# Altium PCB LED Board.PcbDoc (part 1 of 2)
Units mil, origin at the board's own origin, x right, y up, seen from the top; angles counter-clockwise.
Board outline 11968.5 x 3779.53 mil, 2 copper layers (Top Layer, Bottom Layer); 272 components, 796 nets, 779 pads, 57 vias.
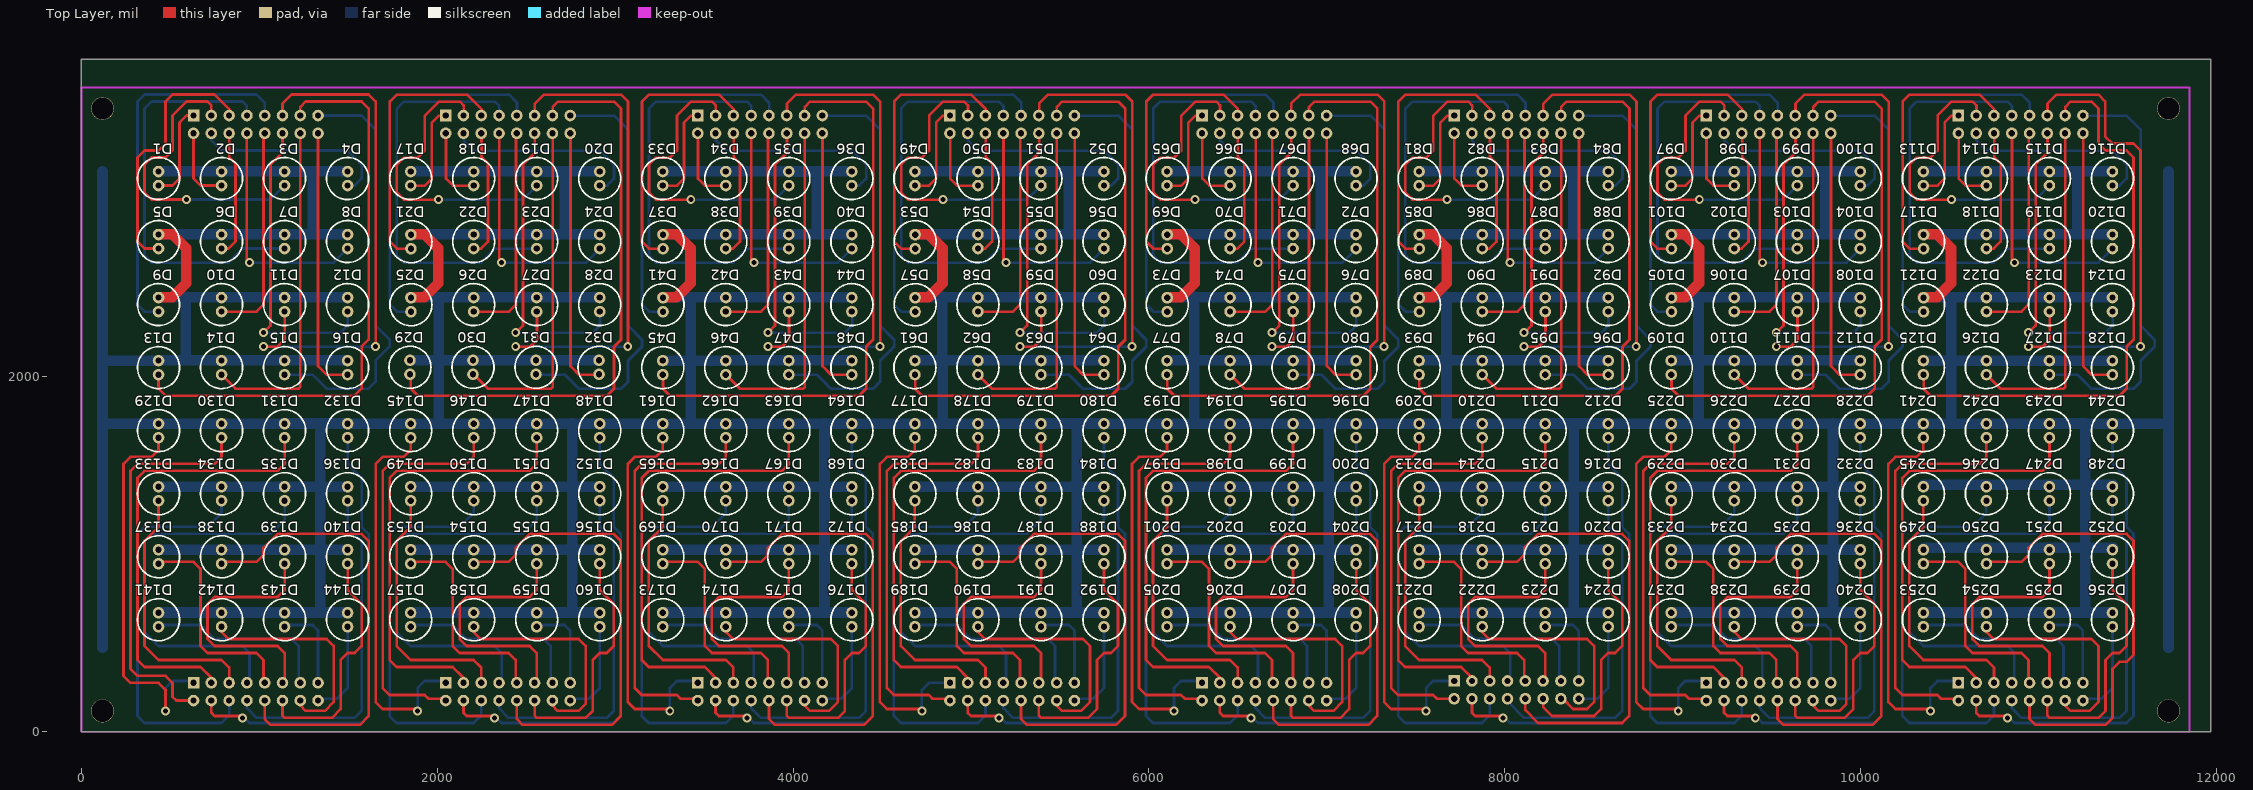
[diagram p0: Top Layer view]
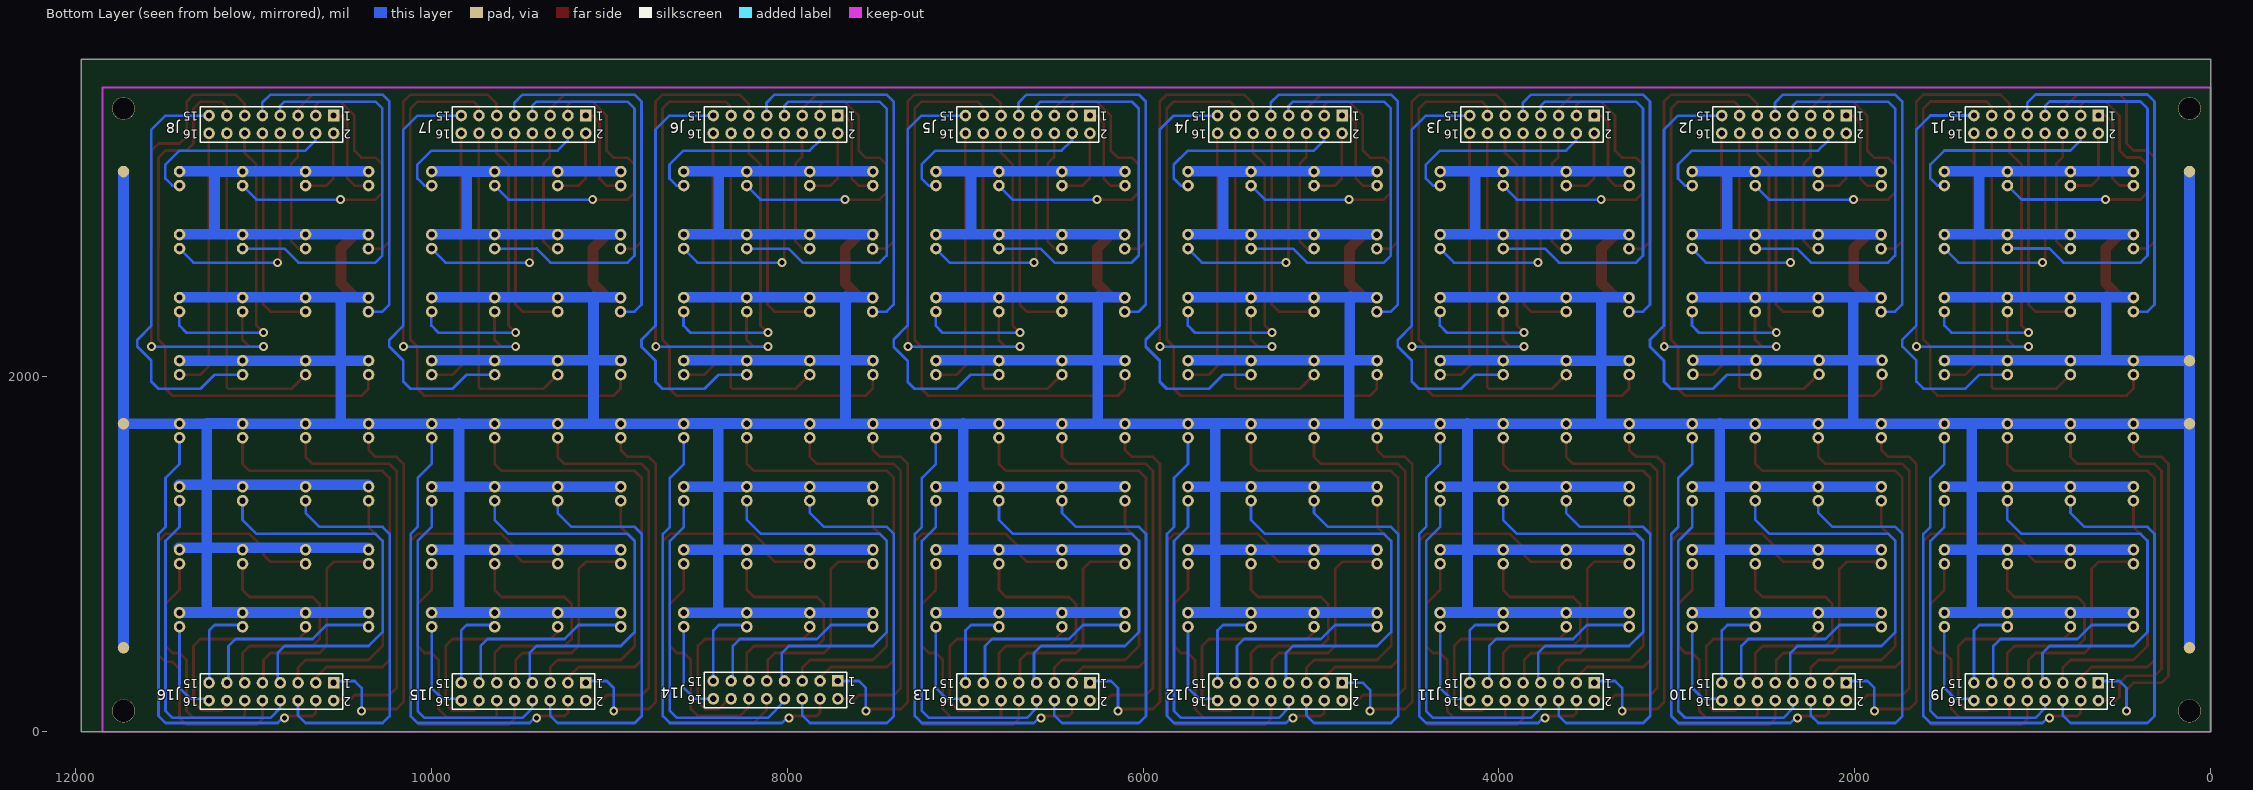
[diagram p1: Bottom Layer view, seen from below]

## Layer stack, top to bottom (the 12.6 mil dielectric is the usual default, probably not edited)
Top Layer: signal copper 1.4
Dielectric: dielectric 12.6, FR-4, Dk 4.8
Bottom Layer: signal copper 1.4

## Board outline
0,0 11968.5,0 11968.5,3779.53 7559.06,3779.53 0,3779.53

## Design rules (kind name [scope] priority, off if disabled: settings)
Clearance [All] p1: gap=10
ComponentClearance [All] p1: gap=10 collisioncheckmode=0
PolygonConnect [All] p1: connectstyle=Relief reliefconductorwidth=10 reliefentries=4 polygonreliefangle="90 Angle"
RoutingLayers [All] p1: top layer=Horizontal bottom layer=Vertical
RoutingVias [All] p1: holewidth=28 width=50 viastyle="Through Hole" minholewidth=28 minwidth=50 maxholewidth=28 maxwidth=50
SolderMaskExpansion [All] p1: expansion=4
TestPointUsage [All] p1: valid=0 allowmultiple=FALSE
Testpoint [All] p1: side=15 testpointundercomponent=TRUE minsize=40 maxsize=100 preferedsize=60 minholesize=0 maxholesize=40 preferedholesize=32 testpointgrid=1 style=1023 order=1234567890
Width Width_1 [InNetClass('A[1..256]')] p1: maxlimit=15 minlimit=15 preferedwidth=15
Width [(InNet('+5'))] p2: maxlimit=60 minlimit=60 preferedwidth=60
16 further rules are at their usual default settings.

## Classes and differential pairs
component class "Input Headers 1": J1 J2 J3 J4 J5 J6 J7 J8 J9
component class "Input Headers 2": J10 J11 J12 J13 J14 J15 J16
component class "Res & Diode 2": D1 D2 D3 D4 D5 D6 D7 D8 D9 D10 D11 D12 D13 D14 D15 D16 D17 D18 D19 D20 D21 D22 D23 D24 D25 D26 D27 D28 D29 D30 D31 D32 D33 D34 D35 D36 D37 D38 D39 D40 D41 D42 D43 D44 D45 D46 D47 D48 D49 D50 D51 D52 D53 D54 D55 D56 D57 D58 D59 D60 D61 D62 D63 D64 D65 D66 D67 D68 D69 D70 D71 D72 D73 D74 D75 D76 D77 D78 D79 D80 D81 D82 D83 D84 D85 D86 D87 D88 D89 D90 D91 D92 D93 D94 D95 D96 D97 D98 D99 D100 D101 D102 D103 D104 D105 D106 D107 D108 D109 D110 D111 D112 D113 D114 D115 D116 D117 D118 D119 D120 D121 D122 D123 D124 D125 D126 D127 D128 D129 D130 D131 D132 D133 D134 D135 D136 D137 D138 D139 D140 D141 D142 D143 D144 D145 D146 D147 D148 D149 D150 D151 D152 D153 D154 D155 D156 D157 D158 D159 D160
net class A[1..256]: A1 A2 A3 A4 A5 A6 A7 A8 A9 A10 A11 A12 A13 A14 A15 A16 A17 A18 A19 A20 A21 A22 A23 A24 A25 A26 A27 A28 A29 A30 A31 A32 A33 A34 A35 A36 A37 A38 A39 A40 A41 A42 A43 A44 A45 A46 A47 A48 A49 A50 A51 A52 A53 A54 A55 A56 A57 A58 A59 A60 A61 A62 A63 A64 A65 A66 A67 A68 A69 A70 A71 A72 A73 A74 A75 A76 A77 A78 A79 A80 A81 A82 A83 A84 A85 A86 A87 A88 A89 A90 A91 A92 A93 A94 A95 A96 A97 A98 A99 A100 A101 A102 A103 A104 A105 A106 A107 A108 A109 A110 A111 A112 A113 A114 A115 A116 A117 A118 A119 A120 A121 A122 A123 A124 A125 A126 A127 A128 A129 A130 A131 A132 A133 A134 A135 A136 A137 A138 A139 A140 A141 A142 A143 A144 A145 A146 A147 A148 A149 A150 A151 A152 A153 A154 A155 A156 A157 A158 A159 A160 A161 A162 A163 A164 A165 A166 A167 A168 A169 A170 A171 A172 A173 A174 A175 A176 A177 A178 A179 A180 A181 A182 A183 A184 A185 A186 A187 A188 A189 A190 A191 A192 A193 A194 A195 A196 A197 A198 A199 A200 A201 A202 A203 A204 A205 A206 A207 A208 A209 A210 A211 A212 A213 A214 A215 A216 A217 A218 A219 A220 A221 A222 A223 A224 A225 A226 A227 A228 A229 A230 A231 A232 A233 A234 A235 A236 A237 A238 A239 A240 A241 A242 A243 A244 A245 A246 A247 A248 A249 A250 A251 A252 A253 A254 A255 A256
component class "Res & Diode 3": D161 D162 D163 D164 D165 D166 D167 D168 D169 D170 D171 D172 D173 D174 D175 D176 D177 D178 D179 D180 D181 D182 D183 D184 D185 D186 D187 D188 D189 D190 D191 D192 D193 D194 D195 D196 D197 D198 D199 D200 D201 D202 D203 D204 D205 D206 D207 D208 D209 D210 D211 D212 D213 D214 D215 D216 D217 D218 D219 D220 D221 D222 D223 D224 D225 D226 D227 D228 D229 D230 D231 D232 D233 D234 D235 D236 D237 D238 D239 D240 D241 D242 D243 D244 D245 D246 D247 D248 D249 D250 D251 D252 D253 D254 D255 D256 R21 R22 R23 R24 R25 R26 R27 R28 R29 R30

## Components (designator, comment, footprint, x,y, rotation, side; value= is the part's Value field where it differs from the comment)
D1 "LED" LED 433.07,3149.61 r180 top
D2 "LED" LED 787.4,3149.61 r180 top
D3 "LED" LED 1141.73,3149.61 r180 top
D4 "LED" LED 1496.06,3149.61 r180 top
D5 "LED" LED 433.07,2795.28 r180 top
D6 "LED" LED 787.4,2795.28 r180 top
D7 "LED" LED 1141.73,2795.28 r180 top
D8 "LED" LED 1496.06,2795.28 r180 top
D9 "LED" LED 433.07,2440.95 r180 top
D10 "LED" LED 787.4,2440.94 r180 top
D11 "LED" LED 1141.73,2440.94 r180 top
D12 "LED" LED 1496.06,2440.94 r180 top
D13 "LED" LED 433.07,2086.61 r180 top
D14 "LED" LED 787.4,2086.61 r180 top
D15 "LED" LED 1141.73,2086.61 r180 top
D16 "LED" LED 1496.06,2086.61 r180 top
D17 "LED" LED 1850.39,3149.61 r180 top
D18 "LED" LED 2204.72,3149.61 r180 top
D19 "LED" LED 2559.06,3149.61 r180 top
D20 "LED" LED 2913.39,3149.61 r180 top
D21 "LED" LED 1851.81,2794.65 r180 top
D22 "LED" LED 2204.72,2795.28 r180 top
D23 "LED" LED 2559.06,2795.28 r180 top
D24 "LED" LED 2913.39,2795.28 r180 top
D25 "LED" LED 1851.81,2440.32 r180 top
D26 "LED" LED 2204.72,2440.94 r180 top
D27 "LED" LED 2559.06,2440.94 r180 top
D28 "LED" LED 2913.39,2440.94 r180 top
D29 "LED" LED 1846.46,2088.5 r180 top
D30 "LED" LED 2200.79,2088.5 r180 top
D31 "LED" LED 2555.12,2088.5 r180 top
D32 "LED" LED 2909.45,2088.5 r180 top
D33 "LED" LED 3267.72,3149.61 r180 top
D34 "LED" LED 3622.05,3149.61 r180 top
D35 "LED" LED 3976.38,3149.61 r180 top
D36 "LED" LED 4330.71,3149.61 r180 top
D37 "LED" LED 3269.13,2794.65 r180 top
D38 "LED" LED 3622.05,2795.28 r180 top
D39 "LED" LED 3976.38,2795.28 r180 top
D40 "LED" LED 4330.71,2795.28 r180 top
D41 "LED" LED 3269.13,2440.32 r180 top
D42 "LED" LED 3622.05,2440.94 r180 top
D43 "LED" LED 3976.38,2440.94 r180 top
D44 "LED" LED 4330.71,2440.94 r180 top
D45 "LED" LED 3267.72,2086.61 r180 top
D46 "LED" LED 3622.05,2086.61 r180 top
D47 "LED" LED 3976.38,2086.61 r180 top
D48 "LED" LED 4330.71,2086.61 r180 top
D49 "LED" LED 4685.04,3149.61 r180 top
D50 "LED" LED 5039.37,3149.61 r180 top
D51 "LED" LED 5393.7,3149.61 r180 top
D52 "LED" LED 5748.03,3149.61 r180 top
D53 "LED" LED 4686.46,2794.65 r180 top
D54 "LED" LED 5039.37,2795.28 r180 top
D55 "LED" LED 5393.7,2795.28 r180 top
D56 "LED" LED 5748.03,2795.28 r180 top
D57 "LED" LED 4686.46,2440.32 r180 top
D58 "LED" LED 5039.37,2440.94 r180 top
D59 "LED" LED 5393.7,2440.94 r180 top
D60 "LED" LED 5748.03,2440.94 r180 top
D61 "LED" LED 4685.04,2086.61 r180 top
D62 "LED" LED 5039.37,2086.61 r180 top
D63 "LED" LED 5393.7,2086.61 r180 top
D64 "LED" LED 5748.03,2086.61 r180 top
D65 "LED" LED 6102.36,3149.61 r180 top
D66 "LED" LED 6456.69,3149.61 r180 top
D67 "LED" LED 6811.02,3149.61 r180 top
D68 "LED" LED 7165.35,3149.61 r180 top
D69 "LED" LED 6103.78,2794.65 r180 top
D70 "LED" LED 6456.69,2795.28 r180 top
D71 "LED" LED 6811.02,2795.28 r180 top
D72 "LED" LED 7165.35,2795.28 r180 top
D73 "LED" LED 6103.78,2440.32 r180 top
D74 "LED" LED 6456.69,2440.94 r180 top
D75 "LED" LED 6811.02,2440.94 r180 top
D76 "LED" LED 7165.35,2440.94 r180 top
D77 "LED" LED 6102.36,2086.61 r180 top
D78 "LED" LED 6456.69,2086.61 r180 top
D79 "LED" LED 6811.02,2086.61 r180 top
D80 "LED" LED 7165.35,2086.61 r180 top
D81 "LED" LED 7519.68,3149.61 r180 top
D82 "LED" LED 7874.02,3149.61 r180 top
D83 "LED" LED 8228.35,3149.61 r180 top
D84 "LED" LED 8582.68,3149.61 r180 top
D85 "LED" LED 7521.1,2794.65 r180 top
D86 "LED" LED 7874.02,2795.28 r180 top
D87 "LED" LED 8228.35,2795.28 r180 top
D88 "LED" LED 8582.68,2795.28 r180 top
D89 "LED" LED 7521.1,2440.32 r180 top
D90 "LED" LED 7874.02,2440.94 r180 top
D91 "LED" LED 8228.35,2440.94 r180 top
D92 "LED" LED 8582.68,2440.94 r180 top
D93 "LED" LED 7519.68,2086.61 r180 top
D94 "LED" LED 7874.02,2086.61 r180 top
D95 "LED" LED 8228.35,2086.61 r180 top
D96 "LED" LED 8582.68,2086.61 r180 top
D97 "LED" LED 8937.01,3149.61 r180 top
D98 "LED" LED 9291.34,3149.61 r180 top
D99 "LED" LED 9645.67,3149.61 r180 top
D100 "LED" LED 10000,3149.61 r180 top
D101 "LED" LED 8938.43,2794.65 r180 top
D102 "LED" LED 9291.34,2795.28 r180 top
D103 "LED" LED 9645.67,2795.28 r180 top
D104 "LED" LED 10000,2795.28 r180 top
D105 "LED" LED 8938.42,2440.32 r180 top
D106 "LED" LED 9291.34,2440.94 r180 top
D107 "LED" LED 9645.67,2440.94 r180 top
D108 "LED" LED 10000,2440.94 r180 top
D109 "LED" LED 8937.01,2086.61 r180 top
D110 "LED" LED 9291.34,2086.61 r180 top
D111 "LED" LED 9645.67,2086.61 r180 top
D112 "LED" LED 10000,2086.61 r180 top
D113 "LED" LED 10354.33,3149.61 r180 top
D114 "LED" LED 10708.66,3149.61 r180 top
D115 "LED" LED 11062.99,3149.61 r180 top
D116 "LED" LED 11417.32,3149.61 r180 top
D117 "LED" LED 10355.75,2794.65 r180 top
D118 "LED" LED 10708.66,2795.28 r180 top
D119 "LED" LED 11062.99,2795.28 r180 top
D120 "LED" LED 11417.32,2795.28 r180 top
D121 "LED" LED 10355.75,2440.32 r180 top
D122 "LED" LED 10708.66,2440.94 r180 top
D123 "LED" LED 11062.99,2440.94 r180 top
D124 "LED" LED 11417.32,2440.94 r180 top
D125 "LED" LED 10354.33,2086.61 r180 top
D126 "LED" LED 10708.66,2086.61 r180 top
D127 "LED" LED 11062.99,2086.61 r180 top
D128 "LED" LED 11417.32,2086.61 r180 top
D129 "LED" LED 433.07,1732.28 r180 top
D130 "LED" LED 787.4,1732.28 r180 top
D131 "LED" LED 1141.73,1732.28 r180 top
D132 "LED" LED 1496.06,1732.28 r180 top
D133 "LED" LED 433.07,1377.95 r180 top
D134 "LED" LED 787.4,1377.95 r180 top
D135 "LED" LED 1141.73,1377.95 r180 top
D136 "LED" LED 1496.06,1377.95 r180 top
D137 "LED" LED 433.07,1023.62 r180 top
D138 "LED" LED 787.4,1023.62 r180 top
D139 "LED" LED 1141.73,1023.62 r180 top
D140 "LED" LED 1496.06,1023.62 r180 top
D141 "LED" LED 433.07,669.29 r180 top
D142 "LED" LED 787.4,669.29 r180 top
D143 "LED" LED 1141.73,669.29 r180 top
D144 "LED" LED 1496.06,669.29 r180 top
D145 "LED" LED 1850.39,1732.28 r180 top
D146 "LED" LED 2204.72,1732.28 r180 top
D147 "LED" LED 2559.06,1732.28 r180 top
D148 "LED" LED 2913.39,1732.28 r180 top
D149 "LED" LED 1850.39,1377.95 r180 top
D150 "LED" LED 2204.72,1377.95 r180 top
D151 "LED" LED 2559.06,1377.95 r180 top
D152 "LED" LED 2913.39,1377.95 r180 top
D153 "LED" LED 1850.39,1023.62 r180 top
D154 "LED" LED 2204.72,1023.62 r180 top
D155 "LED" LED 2559.06,1023.62 r180 top
D156 "LED" LED 2913.39,1023.62 r180 top
D157 "LED" LED 1850.39,669.29 r180 top
D158 "LED" LED 2204.72,669.29 r180 top
D159 "LED" LED 2559.06,669.29 r180 top
D160 "LED" LED 2913.39,669.29 r180 top
D161 "LED" LED 3267.72,1732.28 r180 top
D162 "LED" LED 3622.05,1732.28 r180 top
D163 "LED" LED 3976.38,1732.28 r180 top
D164 "LED" LED 4330.71,1732.28 r180 top
D165 "LED" LED 3267.72,1377.95 r180 top
D166 "LED" LED 3622.05,1377.95 r180 top
D167 "LED" LED 3976.38,1377.95 r180 top
D168 "LED" LED 4330.71,1377.95 r180 top
D169 "LED" LED 3267.72,1023.62 r180 top
D170 "LED" LED 3622.05,1023.62 r180 top
D171 "LED" LED 3976.38,1023.62 r180 top
D172 "LED" LED 4330.71,1023.62 r180 top
D173 "LED" LED 3267.72,669.29 r180 top
D174 "LED" LED 3622.05,669.29 r180 top
D175 "LED" LED 3976.38,669.29 r180 top
D176 "LED" LED 4330.71,669.29 r180 top
D177 "LED" LED 4685.04,1732.28 r180 top
D178 "LED" LED 5039.37,1732.28 r180 top
D179 "LED" LED 5393.7,1732.28 r180 top
D180 "LED" LED 5748.03,1732.28 r180 top
D181 "LED" LED 4685.04,1377.95 r180 top
D182 "LED" LED 5039.37,1377.95 r180 top
D183 "LED" LED 5393.7,1377.95 r180 top
D184 "LED" LED 5748.03,1377.95 r180 top
D185 "LED" LED 4685.04,1023.62 r180 top
D186 "LED" LED 5039.37,1023.62 r180 top
D187 "LED" LED 5393.7,1023.62 r180 top
D188 "LED" LED 5748.03,1023.62 r180 top
D189 "LED" LED 4685.04,669.29 r180 top
D190 "LED" LED 5039.37,669.29 r180 top
D191 "LED" LED 5393.7,669.29 r180 top
D192 "LED" LED 5748.03,669.29 r180 top
D193 "LED" LED 6102.36,1732.28 r180 top
D194 "LED" LED 6456.69,1732.28 r180 top
D195 "LED" LED 6811.02,1732.28 r180 top
D196 "LED" LED 7165.35,1732.28 r180 top
D197 "LED" LED 6102.36,1377.95 r180 top
D198 "LED" LED 6456.69,1377.95 r180 top
D199 "LED" LED 6811.02,1377.95 r180 top
D200 "LED" LED 7165.35,1377.95 r180 top
D201 "LED" LED 6102.36,1023.62 r180 top
D202 "LED" LED 6456.69,1023.62 r180 top
D203 "LED" LED 6811.02,1023.62 r180 top
D204 "LED" LED 7165.35,1023.62 r180 top
D205 "LED" LED 6102.36,669.29 r180 top
D206 "LED" LED 6456.69,669.29 r180 top
D207 "LED" LED 6811.02,669.29 r180 top
D208 "LED" LED 7165.35,669.29 r180 top
D209 "LED" LED 7519.68,1732.28 r180 top
D210 "LED" LED 7874.02,1732.28 r180 top
D211 "LED" LED 8228.35,1732.28 r180 top
D212 "LED" LED 8582.68,1732.28 r180 top
D213 "LED" LED 7519.68,1377.95 r180 top
D214 "LED" LED 7874.02,1377.95 r180 top
D215 "LED" LED 8228.35,1377.95 r180 top
D216 "LED" LED 8582.68,1377.95 r180 top
D217 "LED" LED 7519.68,1023.62 r180 top
D218 "LED" LED 7874.02,1023.62 r180 top
D219 "LED" LED 8228.35,1023.62 r180 top
D220 "LED" LED 8582.68,1023.62 r180 top
D221 "LED" LED 7519.68,669.29 r180 top
D222 "LED" LED 7874.02,669.29 r180 top
D223 "LED" LED 8228.35,669.29 r180 top
D224 "LED" LED 8582.68,669.29 r180 top
D225 "LED" LED 8937.01,1732.28 r180 top
D226 "LED" LED 9291.34,1732.28 r180 top
D227 "LED" LED 9645.67,1732.28 r180 top
D228 "LED" LED 10000,1732.28 r180 top
D229 "LED" LED 8937.01,1377.95 r180 top
D230 "LED" LED 9291.34,1377.95 r180 top
D231 "LED" LED 9645.67,1377.95 r180 top
D232 "LED" LED 10000,1377.95 r180 top
D233 "LED" LED 8937.01,1023.62 r180 top
D234 "LED" LED 9291.34,1023.62 r180 top
D235 "LED" LED 9645.67,1023.62 r180 top
D236 "LED" LED 10000,1023.62 r180 top
D237 "LED" LED 8937.01,669.29 r180 top
D238 "LED" LED 9291.34,669.29 r180 top
D239 "LED" LED 9645.67,669.29 r180 top
D240 "LED" LED 10000,669.29 r180 top
D241 "LED" LED 10354.33,1732.28 r180 top
D242 "LED" LED 10708.66,1732.28 r180 top
D243 "LED" LED 11062.99,1732.28 r180 top
D244 "LED" LED 11417.32,1732.28 r180 top
D245 "LED" LED 10354.33,1377.95 r180 top
D246 "LED" LED 10708.66,1377.95 r180 top
D247 "LED" LED 11062.99,1377.95 r180 top
D248 "LED" LED 11417.32,1377.95 r180 top
D249 "LED" LED 10354.33,1023.62 r180 top
D250 "LED" LED 10708.66,1023.62 r180 top
D251 "LED" LED 11062.99,1023.62 r180 top
D252 "LED" LED 11417.32,1023.62 r180 top
D253 "LED" LED 10354.33,669.29 r180 top
D254 "LED" LED 10708.66,669.29 r180 top
D255 "LED" LED 11062.99,669.29 r180 top
D256 "LED" LED 11417.32,669.29 r180 top
J1 "HDR2X8" HDR2X8 629.92,3464.57 r0 bottom
J2 "HDR2X8" HDR2X8 2047.24,3464.57 r0 bottom
J3 "HDR2X8" HDR2X8 3464.57,3464.57 r0 bottom
J4 "HDR2X8" HDR2X8 4881.89,3464.57 r0 bottom
J5 "HDR2X8" HDR2X8 6299.21,3464.57 r0 bottom
J6 "HDR2X8" HDR2X8 7716.54,3464.57 r0 bottom
J7 "HDR2X8" HDR2X8 9133.86,3464.57 r0 bottom
J8 "HDR2X8" HDR2X8 10551.18,3464.57 r0 bottom
J9 "HDR2X8" HDR2X8 629.92,275.59 r0 bottom
J10 "HDR2X8" HDR2X8 2047.24,275.59 r0 bottom
J11 "HDR2X8" HDR2X8 3464.57,275.59 r0 bottom
J12 "HDR2X8" HDR2X8 4881.89,275.59 r0 bottom
J13 "HDR2X8" HDR2X8 6299.21,275.59 r0 bottom
J14 "HDR2X8" HDR2X8 7716.53,285.83 r0 bottom
J15 "HDR2X8" HDR2X8 9133.86,275.59 r0 bottom
J16 "HDR2X8" HDR2X8 10551.18,275.59 r0 bottom

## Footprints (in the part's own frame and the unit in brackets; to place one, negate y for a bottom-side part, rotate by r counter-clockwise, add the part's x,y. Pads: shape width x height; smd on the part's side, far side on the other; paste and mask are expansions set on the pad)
HDR2X8 [mil]
  rect 65x65 hole 35: 1(0,0)
  round 65 hole 35: 2(0,100) 3(100,0) 4(100,100) 5(200,0) 6(200,100) 7(300,0) 8(300,100) 9(400,0) 10(400,100) 11(500,0) 12(500,100) 13(600,0) 14(600,100) 15(700,0) 16(700,100)
  silkscreen extent -50,-50 750,150
LED [mil]
  round 65 hole 35: 1(0,0) 2(0,78.74)
  silkscreen extent -118,-79 118,157

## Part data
D1 D2 D3 D4 D5 D6 D7 D8 D9 D10 D11 D12 D13 D14 D15 D16 D17 D18 D19 D20 D21 D22 D23 D24 D25 D26 D27 D28 D29 D30 D31 D32 D33 D34 D35 D36 D37 D38 D39 D40 D41 D42 D43 D44 D45 D46 D47 D48 D49 D50 D51 D52 D53 D54 D55 D56 D57 D58 D59 D60 D61 D62 D63 D64 D65 D66 D67 D68 D69 D70 D71 D72 D73 D74 D75 D76 D77 D78 D79 D80 D81 D82 D83 D84 D85 D86 D87 D88 D89 D90 D91 D92 D93 D94 D95 D96 D97 D98 D99 D100 D101 D102 D103 D104 D105 D106 D107 D108 D109 D110 D111 D112 D113 D114 D115 D116 D117 D118 D119 D120 D121 D122 D123 D124 D125 D126 D127 D128 D129 D130 D131 D132 D133 D134 D135 D136 D137 D138 D139 D140 D141 D142 D143 D144 D145 D146 D147 D148 D149 D150 D151 D152 D153 D154 D155 D156 D157 D158 D159 D160 D161 D162 D163 D164 D165 D166 D167 D168 D169 D170 D171 D172 D173 D174 D175 D176 D177 D178 D179 D180 D181 D182 D183 D184 D185 D186 D187 D188 D189 D190 D191 D192 D193 D194 D195 D196 D197 D198 D199 D200 D201 D202 D203 D204 D205 D206 D207 D208 D209 D210 D211 D212 D213 D214 D215 D216 D217 D218 D219 D220 D221 D222 D223 D224 D225 D226 D227 D228 D229 D230 D231 D232 D233 D234 D235 D236 D237 D238 D239 D240 D241 D242 D243 D244 D245 D246 D247 D248 D249 D250 D251 D252 D253 D254 D255 D256: library part LED1, "Typical RED GaAs LED"
J1 J2 J3 J4 J5 J6 J7 J8 J9 J10 J11 J12 J13 J14 J15 J16: library part MHDR1X16, "Header, 16-Pin"

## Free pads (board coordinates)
  round 65 smd far side: 0(118.11,3149.61) 2(118.11,2086.61) 3(118.11,1732.28) 4(118.11,472.44) 5(11732.28,3149.61) 6(11732.28,1732.28) 7(11732.28,472.44)
  round 130 hole 125: ""(118.11,118.11) ""(118.11,3503.94) ""(11732.28,118.11) ""(11732.28,3503.94)

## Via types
v1: diameter 50, hole 28, Top Layer to Bottom Layer, 57 vias

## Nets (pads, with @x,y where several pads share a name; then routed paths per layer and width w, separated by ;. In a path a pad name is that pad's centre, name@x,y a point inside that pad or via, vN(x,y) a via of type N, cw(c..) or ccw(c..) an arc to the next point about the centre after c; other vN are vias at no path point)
+5: D1.1 D2.1 D3.1 D4.1 D5.1 D6.1 D7.1 D8.1 D9.1 D10.1 D11.1 D12.1 D13.1 D14.1 D15.1 D16.1 D17.1 D18.1 D19.1 D20.1 D21.1 D22.1 D23.1 D24.1 D25.1 D26.1 D27.1 D28.1 D29.1 D30.1 D31.1 D32.1 D33.1 D34.1 D35.1 D36.1 D37.1 D38.1 D39.1 D40.1 D41.1 D42.1 D43.1 D44.1 D45.1 D46.1 D47.1 D48.1 D49.1 D50.1 D51.1 D52.1 D53.1 D54.1 D55.1 D56.1 D57.1 D58.1 D59.1 D60.1 D61.1 D62.1 D63.1 D64.1 D65.1 D66.1 D67.1 D68.1 D69.1 D70.1 D71.1 D72.1 D73.1 D74.1 D75.1 D76.1 D77.1 D78.1 D79.1 D80.1 D81.1 D82.1 D83.1 D84.1 D85.1 D86.1 D87.1 D88.1 D89.1 D90.1 D91.1 D92.1 D93.1 D94.1 D95.1 D96.1 D97.1 D98.1 D99.1 D100.1 D101.1 D102.1 D103.1 D104.1 D105.1 D106.1 D107.1 D108.1 D109.1 D110.1 D111.1 D112.1 D113.1 D114.1 D115.1 D116.1 D117.1 D118.1 D119.1 D120.1 D121.1 D122.1 D123.1 D124.1 D125.1 D126.1 D127.1 D128.1 D129.1 D130.1 D131.1 D132.1 D133.1 D134.1 D135.1 D136.1 D137.1 D138.1 D139.1 D140.1 D141.1 D142.1 D143.1 D144.1 D145.1 D146.1 D147.1 D148.1 D149.1 D150.1 D151.1 D152.1 D153.1 D154.1 D155.1 D156.1 D157.1 D158.1 D159.1 D160.1 D161.1 D162.1 D163.1 D164.1 D165.1 D166.1 D167.1 D168.1 D169.1 D170.1 D171.1 D172.1 D173.1 D174.1 D175.1 D176.1 D177.1 D178.1 D179.1 D180.1 D181.1 D182.1 D183.1 D184.1 D185.1 D186.1 D187.1 D188.1 D189.1 D190.1 D191.1 D192.1 D193.1 D194.1 D195.1 D196.1 D197.1 D198.1 D199.1 D200.1 D201.1 D202.1 D203.1 D204.1 D205.1 D206.1 D207.1 D208.1 D209.1 D210.1 D211.1 D212.1 D213.1 D214.1 D215.1 D216.1 D217.1 D218.1 D219.1 D220.1 D221.1 D222.1 D223.1 D224.1 D225.1 D226.1 D227.1 D228.1 D229.1 D230.1 D231.1 D232.1 D233.1 D234.1 D235.1 D236.1 D237.1 D238.1 D239.1 D240.1 D241.1 D242.1 D243.1 D244.1 D245.1 D246.1 D247.1 D248.1 D249.1 D250.1 D251.1 D252.1 D253.1 D254.1 D255.1 D256.1 pad.0 pad.2 pad.3 pad.4 pad.5 pad.6 pad.7 | length 98807.2
  Top Layer w60: D9.1@431.18,2442.2 509.92,2442.2 588.66,2520.94 588.66,2717.8 509.92,2796.54 D5.1@431.18,2796.54 ; D25.1@1848.5,2442.2 1927.25,2442.2 2005.99,2520.94 2005.99,2717.8 1927.24,2796.54 D21.1@1848.5,2796.54 ; D41.1@3265.82,2442.2 3344.57,2442.2 3423.31,2520.94 3423.31,2717.79 3344.57,2796.54 D37.1@3265.83,2796.54 ; D57.1@4683.15,2442.2 4761.89,2442.2 4840.63,2520.94 4840.63,2717.79 4761.89,2796.53 D53.1@4683.15,2796.53 ; D73.1@6100.47,2442.21 6179.21,2442.21 6257.95,2520.95 6257.95,2717.8 6179.21,2796.54 D69.1@6100.47,2796.54 ; D89.1@7517.79,2442.21 7596.54,2442.21 7675.28,2520.95 7675.28,2717.8 7596.54,2796.54 D85.1@7517.8,2796.54 ; D105.1@8935.12,2442.2 9013.86,2442.2 9092.6,2520.94 9092.6,2717.8 9013.86,2796.54 D101.1@8935.12,2796.54 ; D121.1@10352.44,2442.2 10431.18,2442.2 10509.92,2520.95 10509.92,2717.8 10431.18,2796.54 D117.1@10352.44,2796.54
  Bottom Layer w60: pad.4@118.11,472.44 pad.2@118.11,2086.61 ; pad.3@118.11,1732.28 D129.1@433.07,1732.28 D130.1@787.4,1732.28 D131.1@1141.73,1732.28 1142.99,1733.54 1494.8,1733.54 D132.1@1496.06,1732.28 D145.1@1850.39,1732.28 D146.1@2204.72,1732.28 D147.1@2559.05,1732.28 D148.1@2913.38,1732.28 D161.1@3267.72,1732.28 D162.1@3622.05,1732.28 D163.1@3976.38,1732.28 4175.59,1732.28 D164.1@4330.71,1732.28 D177.1@4685.04,1732.28 D178.1@5039.37,1732.28 D179.1@5393.7,1732.28 5394.96,1733.54 5746.77,1733.54 D180.1@5748.03,1732.28 D193.1@6102.36,1732.28 D194.1@6456.69,1732.28 D195.1@6811.02,1732.28 7010.24,1732.28 D196.1@7165.35,1732.28 D209.1@7519.68,1732.28 D210.1@7874.01,1732.28 D211.1@8228.34,1732.28 8229.6,1733.54 8581.42,1733.54 D212.1@8582.68,1732.28 D225.1@8937.01,1732.28 D226.1@9291.34,1732.28 D227.1@9645.67,1732.28 9844.88,1732.28 D228.1@10000,1732.28 D241.1@10354.33,1732.28 D242.1@10708.66,1732.28 11023.62,1732.28 D243.1@11062.99,1732.28 11064.25,1733.54 11263.46,1733.54 ; pad.0@118.11,3149.61 pad.2@118.11,2086.61 ; D13.1@429.13,2088.5 783.46,2088.5 1137.8,2088.5 D16.1@1492.13,2088.5 ; D9.1@431.18,2442.21 785.51,2442.21 1139.84,2442.21 D12.1@1494.17,2442.21 ; D5.1@431.18,2796.54 785.51,2796.54 1139.84,2796.54 D8.1@1494.17,2796.54 ; D1.1@431.18,3150.87 785.51,3150.87 D3.1@1139.84,3150.87 ; D137.1@433.07,1023.62 D140.1@1496.06,1023.62 ; D133.1@433.07,1377.95 D136.1@1496.06,1377.95 ; D13.1@433.07,2086.61 pad.2@118.11,2086.61 ; D141.1@436.69,670.55 D144.1@1499.68,670.55 ; 586.61,2088.5 586.61,2444.1 ; 1227.32,3150.87 1133.07,3149.61 D3.1@1141.73,3149.61 1299.21,3150.19 D4.1@1494.17,3150.87 ; 1299.21,2796.54 1299.21,3149.61 ; 1342.2,680.79 1342.2,1733.54 ; D29.1@1846.46,2088.5 D32.1@2909.45,2088.5 ; D25.1@1848.5,2442.21 2202.83,2442.21 2557.17,2442.2 D28.1@2911.5,2442.2 ; D21.1@1848.5,2796.54 2202.83,2796.54 2557.17,2796.54 D24.1@2911.5,2796.54 ; D17.1@1848.5,3150.87 2202.83,3150.87 D19.1@2557.17,3150.87 ; D153.1@1850.39,1023.62 D156.1@2913.39,1023.62 ; D149.1@1850.39,1377.95 D152.1@2913.39,1377.95 ; D157.1@1854.01,670.55 D160.1@2917,670.55 ; 2007.87,1732.28 2007.87,2442.21 ; 2644.65,3150.87 2550.39,3149.61 D19.1@2559.06,3149.61 2716.53,3150.19 D20.1@2911.5,3150.87 ; 2716.54,2796.54 2716.54,3149.61 ; 2759.53,680.79 2759.53,1733.54 ; D41.1@3265.82,2442.21 3620.15,2442.21 3974.49,2442.2 D44.1@4328.82,2442.2 ; D33.1@3265.82,3150.87 3620.16,3150.87 D35.1@3974.49,3150.87 ; D37.1@3265.83,2796.54 3620.15,2796.54 3974.49,2796.54 D40.1@4328.82,2796.54 ; D169.1@3267.72,1023.62 D172.1@4330.71,1023.62 ; D165.1@3267.72,1377.95 D168.1@4330.71,1377.95 ; D45.1@3267.72,2086.61 D46.1@3622.05,2086.61 ; D173.1@3271.34,670.55 D176.1@4334.33,670.55 ; 3425.2,1732.28 3425.2,2442.21 ; D46.1@3618.11,2088.5 3972.44,2088.5 D48.1@4326.77,2088.5 ; 4061.97,3150.87 3967.72,3149.61 D35.1@3976.38,3149.61 4133.86,3150.19 D36.1@4328.82,3150.87 ; 4133.86,2796.54 4133.86,3149.61 ; 4176.85,680.79 4176.85,1733.54 ; D61.1@4681.1,2088.5 5035.43,2088.5 5389.76,2088.5 D64.1@5744.09,2088.5 ; D57.1@4683.15,2442.21 5037.48,2442.21 5391.81,2442.2 D60.1@5746.14,2442.2 ; D53.1@4683.15,2796.53 5037.48,2796.53 5391.81,2796.53 D56.1@5746.14,2796.53 ; D49.1@4683.15,3150.87 5037.48,3150.87 D51.1@5391.81,3150.87 ; D185.1@4685.04,1023.62 D188.1@5748.03,1023.62 ; D181.1@4685.04,1377.95 D184.1@5748.03,1377.95 ; D189.1@4688.66,670.55 D192.1@5751.65,670.55 ; 4838.58,2088.5 4838.58,2444.1 ; 4842.52,1732.28 4842.52,2088.5 ; 5479.29,3150.86 5385.04,3149.61 D51.1@5393.7,3149.61 5551.18,3150.19 D52.1@5746.14,3150.87 ; 5551.18,2796.53 5551.18,3149.61 ; 5594.17,680.79 5594.17,1733.54 ; D77.1@6098.42,2088.51 6452.76,2088.51 6807.09,2088.51 D80.1@7161.42,2088.51 ; D73.1@6100.47,2442.21 6454.8,2442.21 6809.13,2442.21 D76.1@7163.46,2442.21 ; D69.1@6100.47,2796.54 6454.8,2796.54 6809.13,2796.54 D72.1@7163.46,2796.54 ; D65.1@6100.47,3150.87 6454.8,3150.87 D67.1@6809.13,3150.87 ; D201.1@6102.36,1023.62 D204.1@7165.35,1023.62 ; D197.1@6102.36,1377.95 D200.1@7165.35,1377.95 ; D205.1@6105.98,670.55 D208.1@7168.97,670.55 ; 6255.91,1736.22 6255.91,2444.1 ; 6896.61,3150.87 6802.36,3149.61 D67.1@6811.02,3149.61 6968.5,3150.19 D68.1@7163.46,3150.87 ; 6968.5,2796.54 6968.5,3149.61 ; 7011.5,680.79 7011.5,1733.54 ; D93.1@7515.75,2088.51 7870.08,2088.51 8224.41,2088.51 D96.1@8578.74,2088.51 ; D89.1@7517.79,2442.21 D90.1@7872.12,2442.21 ; D85.1@7517.8,2796.54 7872.12,2796.54 8226.46,2796.54 D88.1@8580.79,2796.54 ; D81.1@7517.79,3150.87 7872.13,3150.87 D83.1@8226.46,3150.87 ; D221.1@7519.68,669.29 D224.1@8582.68,669.29 ; D217.1@7519.68,1023.62 D220.1@8582.68,1023.62 ; D213.1@7519.68,1377.95 D216.1@8582.68,1377.95 ; 7673.23,1736.22 7673.23,2444.1 ; D90.1@7872.13,2442.21 8226.46,2442.21 D92.1@8580.79,2442.21 ; 8313.94,3150.87 8219.69,3149.61 D83.1@8228.35,3149.61 8385.82,3150.19 D84.1@8580.79,3150.87 ; 8385.83,2796.54 8385.83,3149.61 ; 8389.45,680.79 8389.45,1733.54 ; D109.1@8933.07,2088.5 9287.4,2088.5 9641.73,2088.5 D112.1@9996.06,2088.5 ; D105.1@8935.12,2442.21 9289.45,2442.21 9643.78,2442.21 D108.1@9998.11,2442.21 ; D101.1@8935.12,2796.54 9289.45,2796.54 9643.78,2796.54 D104.1@9998.11,2796.54 ; D97.1@8935.12,3150.87 9289.45,3150.87 D99.1@9643.78,3150.87 ; D233.1@8937.01,1023.62 D236.1@10000,1023.62 ; D229.1@8937.01,1377.95 D232.1@10000,1377.95 ; D237.1@8940.63,670.55 D240.1@10003.62,670.55 ; 9090.55,1736.22 9090.55,2444.1 ; 9731.26,3150.87 9637.01,3149.61 D99.1@9645.67,3149.61 9803.15,3150.19 D100.1@9998.11,3150.87 ; 9803.15,2796.54 9803.15,3149.61 ; 9846.14,680.79 9846.14,1733.54 ; D121.1@10352.44,2442.21 10706.77,2442.21 11061.1,2442.21 D124.1@11415.43,2442.21 ; D117.1@10352.44,2796.54 10706.77,2796.54 11061.1,2796.54 D120.1@11415.43,2796.54 ; D113.1@10352.44,3150.87 10706.77,3150.87 D115.1@11061.1,3150.87 ; D125.1@10354.33,2086.61 D126.1@10708.66,2086.61 D127.1@11062.99,2086.61 D128.1@11417.32,2086.61 ; D253.1@10357.95,670.55 D256.1@11420.94,670.55 ; D249.1@10357.95,1035.12 D252.1@11420.94,1035.12 ; D245.1@10357.95,1389.45 D248.1@11420.94,1389.45 ; 10511.81,1732.28 10511.81,2442.21 ; 11148.58,3150.87 11054.33,3149.61 D115.1@11062.99,3149.61 11220.47,3150.19 D116.1@11415.43,3150.87 ; 11220.47,2796.54 11220.47,3149.61 ; 11263.46,680.79 11263.46,1733.54 ; pad.7@11732.28,472.44 pad.6@11732.28,1732.28 ; pad.5@11732.28,3149.61 pad.6@11732.28,1732.28 ; 11263.46,1733.54 11264.72,1732.28 pad.6@11732.28,1732.28
+5: 
A1: D1.2 J1.1 | length 544.4
  Top Layer w15: D1.2@433.07,3070.87 511.81,3070.87 551.18,3110.24 551.18,3425.2 590.55,3464.57 J1.1@629.92,3464.57
A1: 
A1: 
A2: D2.2 J1.2 | length 428.1
  Top Layer w15: J1.2@629.92,3364.57 629.92,3110.24 669.29,3070.87 D2.2@787.4,3070.87
A2: 
A2: 
A3: D3.2 J1.3 | length 1697.8
  Top Layer w15: v1(590.55,2992.13) 393.7,2992.13 354.33,3031.5 354.33,3188.98 393.7,3228.35 472.44,3228.35 511.81,3267.72 511.81,3464.57 590.55,3543.31 708.66,3543.31 729.92,3522.05 J1.3@729.92,3464.57
  Bottom Layer w15: v1(590.55,2992.13) 1062.99,2992.13 D3.2@1141.73,3070.87
A3: 
A3: 
A4: D4.2 J1.4 | length 1114.5
  Bottom Layer w15: J1.4@729.92,3364.57 729.92,3325.2 787.4,3267.72 1496.06,3267.72 1574.8,3188.98 1574.8,3110.24 1535.43,3070.87 D4.2@1496.06,3070.87
A4: 
A4: 
A5: D5.2 J1.5 | length 1477.1
  Top Layer w15: D5.2@433.07,2716.54 354.33,2716.54 314.96,2755.91 314.96,3228.35 354.33,3267.72 433.07,3267.72 472.44,3307.09 472.44,3464.57 472.44,3543.31 511.81,3582.68 748.03,3582.68 829.92,3500.79 J1.5@829.92,3464.57
A5: 
A5: 
A6: D6.2 J1.6 | length 718.7
  Top Layer w15: D6.2@787.4,2716.54 826.77,2716.54 866.14,2755.91 866.14,3195.27 829.92,3231.49 J1.6@829.92,3364.57
A6: 
A6: 
A7: D7.2 J1.7 | length 2319.4
  Bottom Layer w15: J1.7@929.92,3464.57 929.92,3518.9 905.51,3543.31 393.7,3543.31 354.33,3503.94 354.33,2677.17 393.7,2637.8 826.77,2637.8 905.51,2716.54 D7.2@1141.73,2716.54
A7: 
A7: 
A8: D8.2 J1.8 | length 1316.8
  Top Layer w15: J1.8@929.92,3364.57 929.92,2652.76 v1(944.88,2637.8)
  Bottom Layer w15: v1(944.88,2637.8) 1417.32,2637.8 D8.2@1496.06,2716.54
A8: 
A9: D9.2 J1.9 | length 2098.8
  Bottom Layer w15: D9.2@433.07,2362.21 354.33,2362.2 314.96,2401.57 314.96,3543.31 354.33,3582.68 984.25,3582.68 1029.92,3537.01 J1.9@1029.92,3464.57
A9: 
A10: D10.2 J1.10 | length 1218.1
  Top Layer w15: D10.2@787.4,2362.21 984.25,2362.2 1023.62,2401.57 1023.62,3358.27 J1.10@1029.92,3364.57
A10: 
A11: D11.2 J1.11 | length 2927.8
  Top Layer w15: v1(1023.62,2165.35) 1102.36,2165.35 1141.73,2204.72 D11.2@1141.73,2362.21 ; J1.11@1129.92,3464.57 1129.92,3531.49 1181.1,3582.68 1614.17,3582.68 1653.54,3543.31 v1(1653.54,2165.35)
  Bottom Layer w15: v1(1023.62,2165.35) v1(1653.54,2165.35)
A12: D12.2 J1.12 | length 1732
  Top Layer w15: v1(1023.62,2244.09) 1062.99,2283.46 1062.99,3188.98 1129.92,3255.9 J1.12@1129.92,3364.57
  Bottom Layer w15: v1(1023.62,2244.09) 1456.69,2244.09 1496.06,2283.46 D12.2@1496.06,2362.21
A13: D13.2 J1.13 | length 3306
  Top Layer w15: D13.2@433.07,2007.87 433.07,1929.13 472.44,1889.76 1535.43,1889.76 1574.8,1929.13 1574.8,2165.35 1614.17,2204.72 1614.17,3503.94 1574.8,3543.31 1259.84,3543.31 1229.92,3513.38 J1.13@1229.92,3464.57
A14: D14.2 J1.14 | length 1905
  Top Layer w15: D14.2@787.4,2007.87 866.14,1929.13 1220.47,1929.13 1229.92,1938.58 J1.14@1229.92,3364.57
A15: D15.2 J1.15 | length 2399.5
  Bottom Layer w15: D15.2@1141.73,2007.87 1299.21,2007.87 1377.95,1929.13 1614.17,1929.13 1653.54,1968.5 1653.54,2086.61 1732.28,2165.35 1732.28,2204.72 1653.54,2283.46 1653.54,3385.83 1574.8,3464.57 J1.15@1329.92,3464.57
A16: D16.2 J1.16 | length 1494.7
  Top Layer w15: J1.16@1329.92,3364.57 1329.92,2055.91 1377.95,2007.87 D16.2@1496.06,2007.87
A17: D17.2 J2.1 | length 544.4
  Top Layer w15: D17.2@1851.81,3070.24 1930.55,3070.24 1969.92,3109.61 1969.92,3424.57 2009.29,3463.94 J2.1@2048.66,3463.94
A18: D18.2 J2.2 | length 428.1
  Top Layer w15: J2.2@2048.66,3363.94 2048.66,3109.61 2088.03,3070.24 D18.2@2206.14,3070.24
A19: D19.2 J2.3 | length 1697.8
  Top Layer w15: v1@2009.29,2991.5 1812.44,2991.5 1773.07,3030.87 1773.07,3188.35 1812.44,3227.72 1891.18,3227.72 1930.55,3267.09 1930.55,3463.94 2009.29,3542.68 2127.4,3542.68 2148.66,3521.42 J2.3@2148.66,3463.94
  Bottom Layer w15: v1@2009.29,2991.5 2481.73,2991.5 D19.2@2560.47,3070.24
  other v1: 2007.87,2992.13
A20: D20.2 J2.4 | length 1114.5
  Bottom Layer w15: J2.4@2148.66,3363.94 2148.66,3324.57 2206.14,3267.09 2914.8,3267.09 2993.54,3188.35 2993.54,3109.61 2954.17,3070.24 D20.2@2914.8,3070.24
A21: D21.2 J2.5 | length 2310.6
  Top Layer w15: 1732.28,2755.91 1732.28,3543.31 ; D21.2@1851.81,2715.91 1773.07,2715.91 1733.7,2755.28 1733.7,3542.68 1773.07,3582.05 2166.77,3582.05 2248.66,3500.16 J2.5@2248.66,3463.94
A22: D22.2 J2.6 | length 718.7
  Top Layer w15: D22.2@2206.14,2715.91 2245.51,2715.91 2284.88,2755.28 2284.88,3194.64 2248.66,3230.86 J2.6@2248.66,3363.94
A23: D23.2 J2.7 | length 2319.4
  Bottom Layer w15: J2.7@2348.66,3463.94 2348.66,3518.27 2324.25,3542.68 1812.44,3542.68 1773.07,3503.31 1773.07,2676.54 1812.44,2637.17 2245.51,2637.17 2324.25,2715.91 D23.2@2560.47,2715.91
A24: D24.2 J2.8 | length 1316.8
  Top Layer w15: J2.8@2348.66,3363.94 2348.66,2652.13 v1@2363.62,2637.17
  Bottom Layer w15: v1@2363.62,2637.17 2836.06,2637.17 D24.2@2914.8,2715.91
  other v1: 2362.2,2637.8
A25: D25.2 J2.9 | length 3240.5
  Bottom Layer w15: 1732.28,2401.57 1732.28,3543.31 ; D25.2@1851.81,2361.58 1773.07,2361.57 1733.7,2400.94 1733.7,3542.68 1773.07,3582.05 2402.99,3582.05 2448.66,3536.38 J2.9@2448.66,3463.94
A26: D26.2 J2.10 | length 1218.1
  Top Layer w15: D26.2@2206.14,2361.57 2402.99,2361.57 2442.36,2400.94 2442.36,3357.64 J2.10@2448.66,3363.94
A27: D27.2 J2.11 | length 2927.8
  Top Layer w15: v1@2442.36,2164.72 2521.1,2164.72 2560.47,2204.09 D27.2@2560.47,2361.57 ; J2.11@2548.66,3463.94 2548.66,3530.86 2599.84,3582.05 3032.91,3582.05 3072.28,3542.68 v1@3072.28,2164.72
  Bottom Layer w15: v1@2442.36,2164.72 v1@3072.28,2164.72
  other v1: 2440.94,2165.35 3070.87,2165.35
A28: D28.2 J2.12 | length 1732
  Top Layer w15: v1@2442.36,2243.46 2481.73,2282.83 2481.73,3188.35 2548.66,3255.27 J2.12@2548.66,3363.94
  Bottom Layer w15: v1@2442.36,2243.46 2875.43,2243.46 2914.8,2282.83 D28.2@2914.8,2361.57
  other v1: 2440.94,2244.09
A29: D29.2 J2.13 | length 3306
  Top Layer w15: D29.2@1851.81,2007.24 1851.81,1928.5 1891.18,1889.13 2954.17,1889.13 2993.54,1928.5 2993.54,2164.72 3032.91,2204.09 3032.91,3503.31 2993.54,3542.68 2678.58,3542.68 2648.66,3512.75 J2.13@2648.66,3463.94
A30: D30.2 J2.14 | length 1905
  Top Layer w15: D30.2@2206.14,2007.24 2284.88,1928.5 2639.21,1928.5 2648.66,1937.95 J2.14@2648.66,3363.94
A31: D31.2 J2.15 | length 2399.5
  Bottom Layer w15: D31.2@2560.47,2007.24 2717.95,2007.24 2796.69,1928.5 3032.91,1928.5 3072.28,1967.87 3072.28,2085.98 3151.02,2164.72 3151.02,2204.09 3072.28,2282.83 3072.28,3385.2 2993.54,3463.94 J2.15@2748.66,3463.94
A32: D32.2 J2.16 | length 1494.7
  Top Layer w15: J2.16@2748.66,3363.94 2748.66,2055.28 2796.69,2007.24 D32.2@2914.8,2007.24
A33: D33.2 J3.1 | length 544.4
  Top Layer w15: D33.2@3269.13,3070.24 3347.87,3070.24 3387.24,3109.61 3387.24,3424.57 3426.61,3463.94 J3.1@3465.98,3463.94
A34: D34.2 J3.2 | length 428.1
  Top Layer w15: J3.2@3465.98,3363.94 3465.98,3109.61 3505.35,3070.24 D34.2@3623.47,3070.24
A35: D35.2 J3.3 | length 1697.8
  Top Layer w15: v1@3426.61,2991.5 3229.76,2991.5 3190.39,3030.87 3190.39,3188.35 3229.76,3227.72 3308.5,3227.72 3347.87,3267.09 3347.87,3463.94 3426.61,3542.68 3544.72,3542.68 3565.98,3521.42 J3.3@3565.98,3463.94
  Bottom Layer w15: v1@3426.61,2991.5 3899.06,2991.5 D35.2@3977.8,3070.24
  other v1: 3425.2,2992.13
A36: D36.2 J3.4 | length 1114.5
  Bottom Layer w15: J3.4@3565.98,3363.94 3565.98,3324.57 3623.46,3267.09 4332.13,3267.09 4410.87,3188.35 4410.87,3109.61 4371.5,3070.24 D36.2@4332.13,3070.24
A37: D37.2 J3.5 | length 1523.2
  Top Layer w15: D37.2@3269.13,2715.91 3190.39,2715.91 3151.02,2755.28 3151.02,3542.68 3190.39,3582.05 3584.09,3582.05 3665.98,3500.16 J3.5@3665.98,3463.94
A38: D38.2 J3.6 | length 718.7
  Top Layer w15: D38.2@3623.46,2715.91 3662.83,2715.91 3702.2,2755.28 3702.2,3194.64 3665.98,3230.86 J3.6@3665.98,3363.94
A39: D39.2 J3.7 | length 2319.4
  Bottom Layer w15: J3.7@3765.98,3463.94 3765.98,3518.27 3741.57,3542.68 3229.76,3542.68 3190.39,3503.31 3190.39,2676.54 3229.76,2637.17 3662.83,2637.17 3741.57,2715.91 D39.2@3977.8,2715.91
A40: D40.2 J3.8 | length 1316.8
  Top Layer w15: J3.8@3765.98,3363.94 3765.98,2652.13 v1@3780.94,2637.17
  Bottom Layer w15: v1@3780.94,2637.17 4253.39,2637.17 D40.2@4332.13,2715.91
  other v1: 3779.53,2637.8
A41: D41.2 J3.9 | length 2098.8
  Bottom Layer w15: D41.2@3269.13,2361.58 3190.39,2361.57 3151.02,2400.94 3151.02,3542.68 3190.39,3582.05 3820.31,3582.05 3865.98,3536.38 J3.9@3865.98,3463.94
A42: D42.2 J3.10 | length 1218.1
  Top Layer w15: D42.2@3623.47,2361.57 3820.31,2361.57 3859.69,2400.94 3859.69,3357.64 J3.10@3865.98,3363.94
A43: D43.2 J3.11 | length 2927.8
  Top Layer w15: v1@3859.69,2164.72 3938.43,2164.72 3977.8,2204.09 D43.2@3977.8,2361.57 ; J3.11@3965.98,3463.94 3965.98,3530.86 4017.17,3582.05 4450.24,3582.05 4489.61,3542.68 v1@4489.61,2164.72
  Bottom Layer w15: v1@3859.69,2164.72 v1@4489.61,2164.72
  other v1: 3858.27,2165.35 4488.19,2165.35
A44: D44.2 J3.12 | length 1732
  Top Layer w15: v1@3859.69,2243.46 3899.06,2282.83 3899.06,3188.35 3965.98,3255.27 J3.12@3965.98,3363.94
  Bottom Layer w15: v1@3859.69,2243.46 4292.76,2243.46 4332.13,2282.83 D44.2@4332.13,2361.57
  other v1: 3858.27,2244.09
A45: D45.2 J3.13 | length 3306
  Top Layer w15: D45.2@3269.13,2007.24 3269.13,1928.5 3308.5,1889.13 4371.5,1889.13 4410.87,1928.5 4410.87,2164.72 4450.24,2204.09 4450.24,3503.31 4410.87,3542.68 4095.91,3542.68 4065.98,3512.75 J3.13@4065.98,3463.94
A46: D46.2 J3.14 | length 1905
  Top Layer w15: D46.2@3623.46,2007.24 3702.2,1928.5 4056.54,1928.5 4065.98,1937.95 J3.14@4065.98,3363.94
A47: D47.2 J3.15 | length 2399.5
  Bottom Layer w15: D47.2@3977.79,2007.24 4135.28,2007.24 4214.02,1928.5 4450.24,1928.5 4489.61,1967.87 4489.61,2085.98 4568.35,2164.72 4568.35,2204.09 4489.61,2282.83 4489.61,3385.2 4410.87,3463.94 J3.15@4165.98,3463.94
A48: D48.2 J3.16 | length 1494.7
  Top Layer w15: J3.16@4165.98,3363.94 4165.98,2055.28 4214.02,2007.24 D48.2@4332.13,2007.24
A49: D49.2 J4.1 | length 544.4
  Top Layer w15: D49.2@4686.46,3070.24 4765.2,3070.24 4804.57,3109.61 4804.57,3424.57 4843.94,3463.94 J4.1@4883.31,3463.94
A50: D50.2 J4.2 | length 428.1
  Top Layer w15: J4.2@4883.31,3363.94 4883.31,3109.61 4922.68,3070.24 D50.2@5040.79,3070.24
A51: D51.2 J4.3 | length 1697.8
  Top Layer w15: v1@4843.94,2991.5 4647.09,2991.5 4607.72,3030.87 4607.72,3188.35 4647.09,3227.72 4725.83,3227.72 4765.2,3267.09 4765.2,3463.94 4843.94,3542.68 4962.05,3542.68 4983.31,3521.42 J4.3@4983.31,3463.94
  Bottom Layer w15: v1@4843.94,2991.5 5316.38,2991.5 D51.2@5395.12,3070.24
  other v1: 4842.52,2992.13
A52: D52.2 J4.4 | length 1114.5
  Bottom Layer w15: J4.4@4983.31,3363.94 4983.31,3324.57 5040.79,3267.09 5749.45,3267.09 5828.19,3188.35 5828.19,3109.61 5788.82,3070.24 D52.2@5749.45,3070.24
A53: D53.2 J4.5 | length 1523.2
  Top Layer w15: D53.2@4686.46,2715.9 4607.72,2715.91 4568.35,2755.28 4568.35,3542.68 4607.72,3582.05 5001.42,3582.05 5083.31,3500.16 J4.5@5083.31,3463.94
A54: D54.2 J4.6 | length 718.7
  Top Layer w15: D54.2@5040.79,2715.91 5080.16,2715.91 5119.53,2755.28 5119.53,3194.64 5083.31,3230.86 J4.6@5083.31,3363.94
A55: D55.2 J4.7 | length 2319.4
  Bottom Layer w15: J4.7@5183.31,3463.94 5183.31,3518.27 5158.9,3542.68 4647.09,3542.68 4607.72,3503.31 4607.72,2676.54 4647.09,2637.17 5080.16,2637.17 5158.9,2715.91 D55.2@5395.12,2715.91
A56: D56.2 J4.8 | length 1316.8
  Top Layer w15: J4.8@5183.31,3363.94 5183.31,2652.13 v1@5198.27,2637.17
  Bottom Layer w15: v1@5198.27,2637.17 5670.71,2637.17 D56.2@5749.45,2715.91
  other v1: 5196.85,2637.8
A57: D57.2 J4.9 | length 2098.8
  Bottom Layer w15: D57.2@4686.46,2361.57 4607.72,2361.57 4568.35,2400.94 4568.35,3542.68 4607.72,3582.05 5237.64,3582.05 5283.31,3536.38 J4.9@5283.31,3463.94
A58: D58.2 J4.10 | length 1218.1
  Top Layer w15: D58.2@5040.79,2361.57 5237.64,2361.57 5277.01,2400.94 5277.01,3357.64 J4.10@5283.31,3363.94
A59: D59.2 J4.11 | length 2927.8
  Top Layer w15: v1@5277.01,2164.72 5355.75,2164.72 5395.12,2204.09 D59.2@5395.12,2361.57 ; J4.11@5383.31,3463.94 5383.31,3530.86 5434.49,3582.05 5867.56,3582.05 5906.93,3542.68 v1@5906.93,2164.72
  Bottom Layer w15: v1@5277.01,2164.72 v1@5906.93,2164.72
  other v1: 5275.59,2165.35 5905.51,2165.35
A60: D60.2 J4.12 | length 1732
  Top Layer w15: v1@5277.01,2243.46 5316.38,2282.83 5316.38,3188.35 5383.31,3255.27 J4.12@5383.31,3363.94
  Bottom Layer w15: v1@5277.01,2243.46 5710.08,2243.46 5749.45,2282.83 D60.2@5749.45,2361.57
  other v1: 5275.59,2244.09
A61: D61.2 J4.13 | length 3306
  Top Layer w15: D61.2@4686.46,2007.24 4686.46,1928.5 4725.83,1889.13 5788.82,1889.13 5828.19,1928.5 5828.19,2164.72 5867.56,2204.09 5867.56,3503.31 5828.19,3542.68 5513.23,3542.68 5483.31,3512.75 J4.13@5483.31,3463.94
A62: D62.2 J4.14 | length 1905
  Top Layer w15: D62.2@5040.79,2007.24 5119.53,1928.5 5473.86,1928.5 5483.31,1937.95 J4.14@5483.31,3363.94
A63: D63.2 J4.15 | length 2399.5
  Bottom Layer w15: D63.2@5395.12,2007.24 5552.6,2007.24 5631.34,1928.5 5867.56,1928.5 5906.93,1967.87 5906.93,2085.98 5985.67,2164.72 5985.67,2204.09 5906.93,2282.83 5906.93,3385.2 5828.19,3463.94 J4.15@5583.31,3463.94
A64: D64.2 J4.16 | length 1494.7
  Top Layer w15: J4.16@5583.31,3363.94 5583.31,2055.28 5631.34,2007.24 D64.2@5749.45,2007.24
A65: D65.2 J5.1 | length 544.4
  Top Layer w15: D65.2@6103.78,3070.24 6182.52,3070.24 6221.89,3109.61 6221.89,3424.57 6261.26,3463.94 J5.1@6300.63,3463.94
A66: D66.2 J5.2 | length 428.1
  Top Layer w15: J5.2@6300.63,3363.94 6300.63,3109.61 6340,3070.24 D66.2@6458.11,3070.24
A67: D67.2 J5.3 | length 1697.8
  Top Layer w15: v1@6261.26,2991.5 6064.41,2991.5 6025.04,3030.87 6025.04,3188.35 6064.41,3227.72 6143.15,3227.72 6182.52,3267.09 6182.52,3463.94 6261.26,3542.68 6379.37,3542.68 6400.63,3521.42 J5.3@6400.63,3463.94
  Bottom Layer w15: v1@6261.26,2991.5 6733.7,2991.5 D67.2@6812.44,3070.24
  other v1: 6259.84,2992.13
A68: D68.2 J5.4 | length 1114.5
  Bottom Layer w15: J5.4@6400.63,3363.94 6400.63,3324.57 6458.11,3267.09 7166.77,3267.09 7245.51,3188.35 7245.51,3109.61 7206.14,3070.24 D68.2@7166.77,3070.24
A69: D69.2 J5.5 | length 1523.2
  Top Layer w15: D69.2@6103.78,2715.91 6025.04,2715.91 5985.67,2755.28 5985.67,3542.68 6025.04,3582.05 6418.74,3582.05 6500.63,3500.16 J5.5@6500.63,3463.94
A70: D70.2 J5.6 | length 718.7
  Top Layer w15: D70.2@6458.11,2715.91 6497.48,2715.91 6536.85,2755.28 6536.85,3194.64 6500.63,3230.86 J5.6@6500.63,3363.94
A71: D71.2 J5.7 | length 2319.4
  Bottom Layer w15: J5.7@6600.63,3463.94 6600.63,3518.27 6576.22,3542.68 6064.41,3542.68 6025.04,3503.31 6025.04,2676.54 6064.41,2637.17 6497.48,2637.17 6576.22,2715.91 D71.2@6812.44,2715.91
A72: D72.2 J5.8 | length 1316.8
  Top Layer w15: J5.8@6600.63,3363.94 6600.63,2652.13 v1@6615.59,2637.17
  Bottom Layer w15: v1@6615.59,2637.17 7088.03,2637.17 D72.2@7166.77,2715.91
  other v1: 6614.17,2637.8
A73: D73.2 J5.9 | length 2098.8
  Bottom Layer w15: D73.2@6103.78,2361.58 6025.04,2361.57 5985.67,2400.94 5985.67,3542.68 6025.04,3582.05 6654.96,3582.05 6700.63,3536.38 J5.9@6700.63,3463.94
A74: D74.2 J5.10 | length 1218.1
  Top Layer w15: D74.2@6458.11,2361.57 6654.96,2361.57 6694.33,2400.94 6694.33,3357.64 J5.10@6700.63,3363.94
A75: D75.2 J5.11 | length 2927.8
  Top Layer w15: v1@6694.33,2164.72 6773.07,2164.72 6812.44,2204.09 D75.2@6812.44,2361.57 ; J5.11@6800.63,3463.94 6800.63,3530.86 6851.81,3582.05 7284.88,3582.05 7324.25,3542.68 v1@7324.25,2164.72
  Bottom Layer w15: v1@6694.33,2164.72 v1@7324.25,2164.72
  other v1: 6692.91,2165.35 6692.91,2165.35 7322.83,2165.35
A76: D76.2 J5.12 | length 1732
  Top Layer w15: v1@6694.33,2243.46 6733.7,2282.83 6733.7,3188.35 6800.63,3255.27 J5.12@6800.63,3363.94
  Bottom Layer w15: v1@6694.33,2243.46 7127.4,2243.46 7166.77,2282.83 D76.2@7166.77,2361.57
  other v1: 6692.91,2244.09
A77: D77.2 J5.13 | length 3306
  Top Layer w15: D77.2@6103.78,2007.24 6103.78,1928.5 6143.15,1889.13 7206.14,1889.13 7245.51,1928.5 7245.51,2164.72 7284.88,2204.09 7284.88,3503.31 7245.51,3542.68 6930.55,3542.68 6900.63,3512.75 J5.13@6900.63,3463.94
A78: D78.2 J5.14 | length 1905
  Top Layer w15: D78.2@6458.11,2007.24 6536.85,1928.5 6891.18,1928.5 6900.63,1937.95 J5.14@6900.63,3363.94
A79: D79.2 J5.15 | length 2399.5
  Bottom Layer w15: D79.2@6812.44,2007.24 6969.92,2007.24 7048.66,1928.5 7284.88,1928.5 7324.25,1967.87 7324.25,2085.98 7402.99,2164.72 7402.99,2204.09 7324.25,2282.83 7324.25,3385.2 7245.51,3463.94 J5.15@7000.63,3463.94
A80: D80.2 J5.16 | length 1494.7
  Top Layer w15: J5.16@7000.63,3363.94 7000.63,2055.28 7048.66,2007.24 D80.2@7166.77,2007.24
A81: D81.2 J6.1 | length 544.4
  Top Layer w15: D81.2@7521.1,3070.24 7599.84,3070.24 7639.21,3109.61 7639.21,3424.57 7678.58,3463.94 J6.1@7717.95,3463.94
A82: D82.2 J6.2 | length 428.1
  Top Layer w15: J6.2@7717.95,3363.94 7717.95,3109.61 7757.32,3070.24 D82.2@7875.43,3070.24
A83: D83.2 J6.3 | length 1697.8
  Top Layer w15: v1@7678.58,2991.5 7481.73,2991.5 7442.36,3030.87 7442.36,3188.35 7481.73,3227.72 7560.47,3227.72 7599.84,3267.09 7599.84,3463.94 7678.58,3542.68 7796.69,3542.68 7817.95,3521.42 J6.3@7817.95,3463.94
  Bottom Layer w15: v1@7678.58,2991.5 8151.02,2991.5 D83.2@8229.76,3070.24
  other v1: 7677.17,2992.13
A84: D84.2 J6.4 | length 1114.5
  Bottom Layer w15: J6.4@7817.95,3363.94 7817.95,3324.57 7875.43,3267.09 8584.09,3267.09 8662.83,3188.35 8662.83,3109.61 8623.46,3070.24 D84.2@8584.1,3070.24
A85: D85.2 J6.5 | length 1523.2
  Top Layer w15: D85.2@7521.1,2715.91 7442.36,2715.91 7402.99,2755.28 7402.99,3542.68 7442.36,3582.05 7836.06,3582.05 7917.95,3500.16 J6.5@7917.95,3463.94
A86: D86.2 J6.6 | length 718.7
  Top Layer w15: D86.2@7875.43,2715.91 7914.8,2715.91 7954.17,2755.28 7954.17,3194.64 7917.95,3230.86 J6.6@7917.95,3363.94
A87: D87.2 J6.7 | length 2319.4
  Bottom Layer w15: J6.7@8017.95,3463.94 8017.95,3518.27 7993.54,3542.68 7481.73,3542.68 7442.36,3503.31 7442.36,2676.54 7481.73,2637.17 7914.8,2637.17 7993.54,2715.91 D87.2@8229.76,2715.91
A88: D88.2 J6.8 | length 1316.8
  Top Layer w15: J6.8@8017.95,3363.94 8017.95,2652.13 v1@8032.91,2637.17
  Bottom Layer w15: v1@8032.91,2637.17 8505.35,2637.17 D88.2@8584.09,2715.91
  other v1: 8031.5,2637.8
A89: D89.2 J6.9 | length 2098.8
  Bottom Layer w15: D89.2@7521.1,2361.58 7442.36,2361.57 7402.99,2400.94 7402.99,3542.68 7442.36,3582.05 8072.28,3582.05 8117.95,3536.38 J6.9@8117.95,3463.94
A90: D90.2 J6.10 | length 1218.1
  Top Layer w15: D90.2@7875.43,2361.57 8072.28,2361.57 8111.65,2400.94 8111.65,3357.64 J6.10@8117.95,3363.94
